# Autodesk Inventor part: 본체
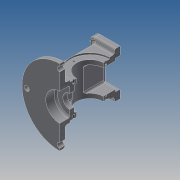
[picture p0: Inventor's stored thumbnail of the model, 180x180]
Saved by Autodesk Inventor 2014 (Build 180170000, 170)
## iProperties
Created: 2019-08
Part Number: 본체
Material: Generic
Document SubType Name: Modeling
Designer: kb542-16
Density: 1 g/cm^3
Appearance: Default
Author: kb542-16
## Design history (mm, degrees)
sketch "스케치1"
  geometry: L1 (37, -33)-(-37, -33); L2 (-37, -33)-(-37, 33); L3 (-37, 33)-(37, 33); L4 (37, 33)-(37, -33); L5 (37, -33)-(-37, 33); L6 (-37, -33)-(37, 33); 1 further point
  constraints: 12 end point, 2 midpoint, 2 parallel, 1 horizontal, 1 perpendicular
  dimensions: "d0" = 66 distance of L1.end L2.end; "d1" = 74 distance of L2.end L3.end
extrude "돌출1" new body sketch "스케치1" distance "d2" = 88; taper "d3" = 0 deg
sketch "스케치2"
  geometry: L1 (46, -41)-(-46, -41); L2 (-46, -41)-(-46, 41); L3 (-46, 41)-(46, 41); L4 (46, 41)-(46, -41); L5 (46, -41)-(-46, 41); L6 (-46, -41)-(46, 41); 1 further point
  constraints: 12 end point, 2 midpoint, 2 parallel, 1 horizontal, 1 perpendicular
  dimensions: "d4" = 92 distance of L2.end L3.end; "d5" = 82 distance of L3.end L1.start
extrude "돌출2" join sketch "스케치2" distance "d6" = 10; taper "d7" = 0 deg
sketch "스케치3"
  geometry: C1 r 67.5 at (0, 0); 1 further point
  constraints: 1 centre point, 1 coincident
  dimensions: "d8" = 135 diameter of C1
extrude "돌출3" join sketch "스케치3" distance "d9" = 10; taper "d10" = 0 deg
sketch "스케치4"
  geometry: C1 r 67.5 at (0, 0) reference; C2 r 25 at (0, 0)
  constraints: 1 centre point, 1 coincident
  dimensions: "d11" = 50 diameter of C2
extrude "돌출4" cut sketch "스케치4" distance "d12" = 18; taper "d13" = 0 deg
sketch "스케치5"
  geometry: C1 r 25 at (0, 0) reference; C2 r 12.5 at (0, 0)
  constraints: 1 centre point, 1 coincident
  dimensions: "d14" = 25 diameter of C2
extrude "돌출5" cut sketch "스케치5" stored distance "d15" = 18; taper "d16" = 0 deg
sketch "스케치6"
  geometry: L1 (74, -88)-(0, -88) reference; L2 (-30.5, -98)-(104.5, -98) reference; C1 r 35 at (37, -44); 2 further points
  constraints: 1 centre point, 1 midpoint, 1 vertical alignment
  dimensions: "d17" = 70 diameter of C1; "d18" = 54 distance from line of L2 C1.centre
extrude "돌출6" cut sketch "스케치6" distance "d19" = 3; taper "d20" = 0 deg
sketch "스케치7"
  geometry: C1 r 35 at (0, 0) reference; C2 r 24 at (0, 0); 1 further point
  constraints: 1 centre point, 1 coincident
  dimensions: "d21" = 48 diameter of C2
extrude "돌출7" cut sketch "스케치7" stored distance "d22" = 3; taper "d23" = 0 deg
sketch "스케치8"
  geometry: L1 (-26, -26)-(26, -26); L2 (26, -26)-(26, 26); L3 (26, 26)-(-26, 26); L4 (-26, 26)-(-26, -26); L5 (-26, -26)-(26, 26); L6 (26, -26)-(-26, 26); C1 r 12.5 at (0, 0) reference
  constraints: 12 end point, 2 midpoint, 2 parallel, 1 horizontal, 1 perpendicular
  dimensions: "d24" = 52 distance of L2.end L3.end; "d25" = 52 distance of L3.end L1.start
extrude "돌출8" cut sketch "스케치8" distance "d26" = 8; taper "d27" = 0 deg
sketch "스케치10"
  geometry: L1 (-22, -22)-(22, -22); L2 (22, -22)-(22, 22); L3 (22, 22)-(-22, 22); L4 (-22, 22)-(-22, -22); L5 (-22, -22)-(22, 22); L6 (22, -22)-(-22, 22); C1 r 12.5 at (0, 0) reference
  constraints: 12 end point, 2 midpoint, 2 parallel, 1 horizontal, 1 perpendicular
  dimensions: "d32" = 44 distance of L3.end L2.end; "d33" = 44 distance of L3.end L1.start
extrude "돌출10" cut sketch "스케치10" distance "d34" = 74; taper "d35" = 0 deg
sketch "스케치11"
  geometry: C1 r 24 at (0, 0) reference; 2 further points
  constraints: 1 vertical alignment
  dimensions: "d36" = 29 distance of C1.centre point (0, 29)
hole "구멍1" sketch "스케치11" at (0, 29) diameter "d37" = 3.242; stored, may be unused: countersink angle "d41" = 90 deg, drill point angle "d43" = 118 deg; dims "d38" = 4, "d39" = 4, "d40" = 2, "d42" = 6
sketch "스케치13"
  geometry: 5 further points
  constraints: 1 horizontal alignment, 1 vertical alignment
  dimensions: "d56" = 72 distance of point (36, 31) point (-36, 31); "d57" = 62 distance of point (-36, 31) point (-36, -31); "d58" = 72 distance of point (36, -31) point (-36, -31); "d59" = 62 distance of point (36, 31) point (36, -31); "d61" = 31 vertical distance of point (0, 0) point (-36, -31); "d62" = 36 horizontal distance of point (0, 0) point (-36, -31)
hole "구멍3" sketch "스케치13" at (-36, 31), (36, 31), (36, -31), (-36, -31) diameter "d63" = 3.242; stored, may be unused: countersink angle "d67" = 90 deg, drill point angle "d69" = 118 deg; dims "d64" = 4, "d65" = 4, "d66" = 2, "d68" = 6
sketch "스케치14" dims "d70" = 118
  geometry: C1 r 67.5 at (0, 0) reference; C2 r 4.5 at (0, 59); 1 further point
  constraints: 2 vertical alignment, 1 centre point, 1 coincident, 2 other
  dimensions: "d71" = 9 diameter of C2
extrude "돌출11" cut sketch "스케치14" stored distance "d72" = 74; taper "d73" = 0 deg
sketch "스케치15" dims "d77" = 118
  geometry: C1 r 67.5 at (0, 0) reference; 2 further points
  constraints: 2 horizontal alignment, 1 coincident, 3 other
feature "엠보싱1" sketch "스케치15" dims "d0" = 66, "d1" = 74, "d78" = 0.5, "d79" = 0
chamfer "모따기1" distance "d80" = 3; stored, may be unused: second distance "d81" = 2, angle "d82" = 45 deg
fillet "모깎기1" dims "d83" = 10
fillet "모깎기2" dims "d84" = 3
fillet "모깎기3" dims "d85" = 3
chamfer "모따기2" distance "d86" = 1; stored, may be unused: second distance "d87" = 2, angle "d88" = 45 deg
sketch "스케치16"
  geometry: L1 (-97.5, -13)-(37.5, -13) reference; L2 (-61, 95)-(1, 95) reference; 4 further points
  constraints: 2 vertical alignment, 1 midpoint
  dimensions: "d89" = 37 distance from line of point (-30, 24) L1; "d90" = 43 distance of point (-30, 67) point (-30, 24)
hole "구멍5" sketch "스케치16" diameter "d98" = 4.917; stored, may be unused: countersink angle "d102" = 90 deg, drill point angle "d104" = 118 deg; dims "d99" = 4, "d100" = 4, "d101" = 2, "d103" = 6
hole "구멍6" sketch "스케치16" diameter "d105" = 4.917; stored, may be unused: countersink angle "d109" = 90 deg, drill point angle "d111" = 118 deg; dims "d106" = 4, "d107" = 4, "d108" = 2, "d110" = 6
fillet "모깎기4" dims "d112" = 3
fillet "모깎기5" dims "d113" = 3
fillet "모깎기6" dims "d114" = 3
node "솔리드1"
pattern_circular "원형 패턴1" dims angle "d45" = 360 deg
mirror "대칭1"
pattern_circular "원형 패턴2" dims angle "d75" = 180 deg
